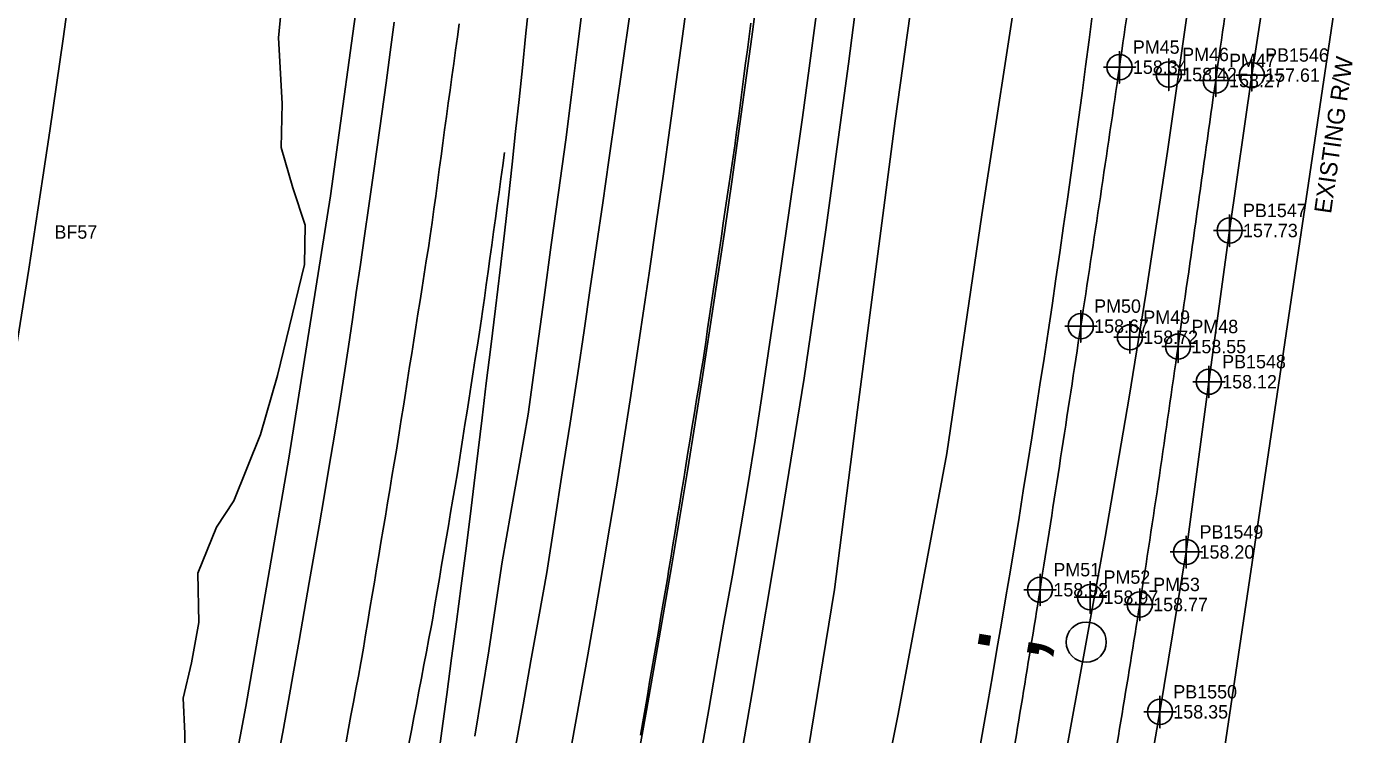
# Model space of a CAD drawing. Extents: x 2262665 to 2270527, y 505476 to 514960.
# Drawn here: x 2266157.3 to 2266407.4, y 509846.4 to 509978.6 of the extents above; entities that cross this region are included whole.
import ezdxf

# ---------------------------------------------------------------- set-up
doc = ezdxf.new("R2010")
doc.units = 0
for name, color, linetype in [('Exist DTM Crownline Cogo Elevation', 7, 'Continuous'), ('Exist DTM Crownline Cogo Number', 7, 'Continuous'), ('Exist DTM Crownline Cogo Point CELL', 7, 'Continuous'), ('Exist Guardrail', 7, 'Continuous'), ('Exist Horizontal Alignment', 7, 'Continuous'), ('Exist Property Corner Cogo Number', 7, 'Continuous'), ('Exist Right of Way Control of Access Line', 7, 'Continuous'), ('Exist Right of Way Line', 7, 'Continuous'), ('Exist Right of Way Line Text', 7, 'Continuous'), ('Exist Roads EOP', 7, 'Continuous'), ('Exist Roads EOP Cogo Elevation', 7, 'Continuous'), ('Exist Roads EOP Cogo Number', 7, 'Continuous'), ('Exist Roads EOP Cogo Point CELL', 7, 'Continuous'), ('Exist Roads EOT', 7, 'Continuous'), ('Exist Structure Minor Paved Ditch or Gutter', 7, 'Continuous'), ('Exist Utilities Water UG Line SUE LOS B', 7, 'Continuous'), ('Exist Utilities Water UG Line SUE LOS B Cogo Elevation', 7, 'Continuous'), ('Exist Utilities Water UG Line SUE LOS B Cogo Number', 7, 'Continuous'), ('Exist Utilities Water UG Line SUE LOS B Cogo Point CELL', 7, 'Continuous'), ('Exist Vegetation Hedge Row', 7, 'Continuous'), ('Exist Vegetation Woods Line', 7, 'Continuous'), ('Scratch_Level_1', 7, 'Continuous')]:
    doc.layers.add(name, color=color, linetype=linetype)

msp = doc.modelspace()

# ---------------------------------------------------------------- linework, layer by layer
at = {"layer": 'Exist DTM Crownline Cogo Point CELL'}
for points in [[(2266370.67, 509972.68), (2266370.67, 509966.68), (2266370.67, 509969.68), (2266373.67, 509969.68), (2266367.67, 509969.68)], [(2266363.41, 509923.59), (2266363.41, 509917.59), (2266363.41, 509920.59), (2266366.41, 509920.59), (2266360.41, 509920.59)], [(2266355.98, 509875.03), (2266355.98, 509869.03), (2266355.98, 509872.03), (2266358.98, 509872.03), (2266352.98, 509872.03)]]:
    msp.add_lwpolyline(points, dxfattribs=at)
for centre in [(2266370.67, 509969.68), (2266363.41, 509920.59), (2266355.98, 509872.03)]:
    msp.add_circle(centre, 2.34, dxfattribs=at)
at = {"layer": 'Exist Guardrail'}
for points in [[(2266160.84, 509676.92), (2266165.08, 509693.72), (2266174.04, 509733.83), (2266182.53, 509771.8), (2266190.31, 509809.74), (2266198.21, 509851.61), (2266206.26, 509898.03), (2266214.05, 509947), (2266219.83, 509989.18), (2266225.03, 510032.89), (2266230.21, 510077.92), (2266233.96, 510117.98), (2266237.41, 510165.42), (2266240.43, 510208.57), (2266242.31, 510234.33)], [(2266334.39, 510233.28), (2266333.37, 510212.85), (2266331.81, 510184.43), (2266330.09, 510160.21), (2266327.64, 510127.74), (2266324.86, 510095.33), (2266321.82, 510063.37), (2266317.9, 510027.29), (2266314.72, 510001.82), (2266310.83, 509971.64), (2266306.61, 509940.64), (2266302.52, 509912.93), (2266297.99, 509884.97), (2266292.86, 509854.22), (2266287.18, 509821.48), (2266279.3, 509783.63), (2266270.08, 509740.16), (2266261.99, 509703.88), (2266253.35, 509666.68), (2266250.16, 509652.66)]]:
    msp.add_lwpolyline(points, dxfattribs=at)
at = {"layer": 'Exist Horizontal Alignment'}
msp.add_line((2266331.51, 509734.43), (2266355.25, 509863.64), dxfattribs=at)
msp.add_circle((2266355.25, 509863.64), 3.75, dxfattribs=at)
for centre, radius, start, end in [((2263773.45, 510337.89), 2625, 349.59137, 358.85635), ((2263436.25, 510359.19), 2882, 309.60499, 355.6461)]:
    msp.add_arc(centre, radius, start, end, dxfattribs=at)
at = {"layer": 'Exist Right of Way Control of Access Line'}
msp.add_arc((2263436.25, 510359.19), 2754.56, 309.60499, 355.6461, dxfattribs=at)
at = {"layer": 'Exist Right of Way Line'}
msp.add_line((2266407.37, 510020.95), (2266379.14, 509830.83), dxfattribs=at)
at = {"layer": 'Exist Roads EOP'}
for points in [[(2266259.16, 509844.7), (2266260.64, 509852.99), (2266262.11, 509861.26), (2266263.56, 509869.51), (2266264.95, 509877.53), (2266266.26, 509885.3), (2266267.52, 509892.95), (2266268.73, 509900.58), (2266270.02, 509908.91), (2266271.4, 509917.99), (2266272.83, 509927.58), (2266273.56, 509932.54), (2266274.97, 509942.22), (2266276.24, 509951.15), (2266277.44, 509959.71), (2266278.63, 509968.3), (2266279.81, 509976.82), (2266280.96, 509985.2)], [(2266251.1, 509982.65), (2266250.5, 509976.8), (2266249.9, 509970.94), (2266249.28, 509965.01), (2266248.64, 509959), (2266247.98, 509952.91), (2266247.28, 509946.63), (2266246.53, 509940.05), (2266245.72, 509933.17), (2266244.86, 509925.99), (2266243.99, 509918.83), (2266243.16, 509912.02), (2266242.38, 509905.54), (2266241.64, 509899.41), (2266240.9, 509893.36), (2266240.13, 509887.12), (2266239.31, 509880.71), (2266238.45, 509874.12), (2266237.57, 509867.41), (2266236.67, 509860.66), (2266235.77, 509853.87), (2266234.85, 509847.03), (2266233.91, 509840.1)], [(2266225.97, 509979.46), (2266225.22, 509973.86), (2266224.44, 509968.11), (2266223.64, 509962.31), (2266222.83, 509956.54), (2266222.03, 509950.82), (2266221.21, 509945.13), (2266220.41, 509939.56), (2266219.63, 509934.16), (2266218.87, 509928.94), (2266218.14, 509923.9), (2266217.39, 509918.84), (2266216.58, 509913.55), (2266215.71, 509908.03), (2266214.78, 509902.27), (2266213.82, 509896.49), (2266212.88, 509890.85), (2266211.94, 509885.37), (2266211.02, 509880.04), (2266210.09, 509874.75), (2266209.15, 509869.38), (2266208.19, 509863.93), (2266207.21, 509858.4), (2266206.2, 509852.73), (2266205.12, 509846.83), (2266203.98, 509840.72)], [(2266304.76, 509980.71), (2266303.5, 509970.88), (2266302.24, 509961.65), (2266301.01, 509952.94), (2266299.82, 509944.68), (2266298.63, 509936.57), (2266297.41, 509928.3), (2266296.14, 509919.66), (2266294.76, 509910.42), (2266293.38, 509901.36), (2266292.09, 509893.28), (2266290.73, 509885.2), (2266289.13, 509876.12), (2266287.49, 509866.98), (2266286.04, 509858.71), (2266284.71, 509851.04), (2266283.4, 509843.7)]]:
    msp.add_lwpolyline(points, dxfattribs=at)
for points in [[(2266387.02, 510213.77), (2266383.96, 510164.13), (2266379.47, 510113.75), (2266374, 510066.49), (2266368.14, 510019.35), (2266361.46, 509971.05), (2266354.23, 509922.66), (2266346.61, 509873.42), (2266339.5, 509830.06)], [(2266405.94, 510212.74), (2266402.45, 510162.89), (2266397.89, 510112.57), (2266392.37, 510064.61), (2266386.2, 510016.82), (2266379.43, 509968.56), (2266372.4, 509918.85), (2266365.25, 509870.66), (2266358.04, 509827.1)]]:
    msp.add_spline(points, degree=3, dxfattribs=at)
at = {"layer": 'Exist Roads EOP Cogo Point CELL'}
for points in [[(2266361.46, 509974.05), (2266361.46, 509968.05), (2266361.46, 509971.05), (2266364.46, 509971.05), (2266358.46, 509971.05)], [(2266379.43, 509971.56), (2266379.43, 509965.56), (2266379.43, 509968.56), (2266382.43, 509968.56), (2266376.43, 509968.56)], [(2266354.23, 509925.66), (2266354.23, 509919.66), (2266354.23, 509922.66), (2266357.23, 509922.66), (2266351.23, 509922.66)], [(2266372.4, 509921.85), (2266372.4, 509915.85), (2266372.4, 509918.85), (2266375.4, 509918.85), (2266369.4, 509918.85)], [(2266346.61, 509876.42), (2266346.61, 509870.42), (2266346.61, 509873.42), (2266349.61, 509873.42), (2266343.61, 509873.42)], [(2266365.25, 509873.66), (2266365.25, 509867.66), (2266365.25, 509870.66), (2266368.25, 509870.66), (2266362.25, 509870.66)]]:
    msp.add_lwpolyline(points, dxfattribs=at)
for centre in [(2266361.46, 509971.05), (2266379.43, 509968.56), (2266354.23, 509922.66), (2266372.4, 509918.85), (2266346.61, 509873.42), (2266365.25, 509870.66)]:
    msp.add_circle(centre, 2.34, dxfattribs=at)
at = {"layer": 'Exist Roads EOT'}
for points in [[(2266292.57, 509979.25), (2266292.25, 509976.77), (2266291.93, 509974.29), (2266291.6, 509971.82), (2266291.28, 509969.34), (2266290.96, 509966.86), (2266290.63, 509964.38), (2266290.31, 509961.9), (2266289.99, 509959.42), (2266289.66, 509956.94), (2266289.64, 509956.76), (2266289.27, 509954.28), (2266288.91, 509951.81), (2266288.54, 509949.34), (2266288.17, 509946.86), (2266287.81, 509944.39), (2266287.44, 509941.92), (2266287.08, 509939.45), (2266286.71, 509936.97), (2266286.34, 509934.5), (2266285.98, 509932.03), (2266285.61, 509929.55), (2266285.25, 509927.08), (2266284.88, 509924.61), (2266284.51, 509922.14), (2266284.15, 509919.66), (2266283.78, 509917.19), (2266283.66, 509916.34), (2266283.26, 509913.88), (2266282.85, 509911.41), (2266282.45, 509908.94), (2266282.05, 509906.47), (2266281.65, 509904.01), (2266281.25, 509901.54), (2266280.84, 509899.07), (2266280.44, 509896.61), (2266280.04, 509894.14), (2266279.64, 509891.67), (2266279.23, 509889.2), (2266278.83, 509886.74), (2266278.43, 509884.27), (2266278.03, 509881.8), (2266277.63, 509879.34), (2266277.22, 509876.87), (2266277.06, 509875.84), (2266276.63, 509873.37), (2266276.21, 509870.91), (2266275.79, 509868.45), (2266275.37, 509865.98), (2266274.94, 509863.52), (2266274.52, 509861.05), (2266274.1, 509858.59), (2266273.68, 509856.13), (2266273.25, 509853.66), (2266272.83, 509851.2), (2266272.41, 509848.74), (2266271.98, 509846.27)], [(2266216.96, 509845.02), (2266217.42, 509847.47), (2266217.88, 509849.93), (2266218.34, 509852.39), (2266218.8, 509854.84), (2266219.26, 509857.3), (2266219.72, 509859.76), (2266219.78, 509860.06), (2266220.19, 509862.53), (2266220.6, 509864.99), (2266221.01, 509867.46), (2266221.43, 509869.93), (2266221.84, 509872.39), (2266222.25, 509874.86), (2266222.66, 509877.32), (2266223.07, 509879.79), (2266223.48, 509882.25), (2266223.9, 509884.72), (2266224.31, 509887.18), (2266224.72, 509889.65), (2266225.13, 509892.11), (2266225.54, 509894.58), (2266225.96, 509897.04), (2266226.37, 509899.51), (2266226.5, 509900.28), (2266226.89, 509902.75), (2266227.28, 509905.22), (2266227.66, 509907.69), (2266228.05, 509910.16), (2266228.44, 509912.63), (2266228.83, 509915.1), (2266229.22, 509917.57), (2266229.61, 509920.03), (2266230, 509922.5), (2266230.39, 509924.97), (2266230.78, 509927.44), (2266231.17, 509929.91), (2266231.56, 509932.38), (2266231.95, 509934.85), (2266232.34, 509937.32), (2266232.69, 509939.53), (2266233.02, 509942.01), (2266233.36, 509944.49), (2266233.7, 509946.97), (2266234.03, 509949.44), (2266234.37, 509951.92), (2266234.71, 509954.4), (2266235.05, 509956.87), (2266235.38, 509959.35), (2266235.72, 509961.83), (2266236.06, 509964.3), (2266236.4, 509966.78), (2266236.73, 509969.26), (2266237.07, 509971.73), (2266237.41, 509974.21), (2266237.75, 509976.69), (2266238.08, 509979.16)], [(2266246.58, 509955.13), (2266246.24, 509952.66), (2266245.89, 509950.18), (2266245.55, 509947.71), (2266245.21, 509945.23), (2266244.86, 509942.75), (2266244.52, 509940.28), (2266244.18, 509937.8), (2266243.83, 509935.33), (2266243.49, 509932.85), (2266243.15, 509930.37), (2266242.8, 509927.9), (2266242.46, 509925.42), (2266242.27, 509924.04), (2266241.88, 509921.57), (2266241.49, 509919.1), (2266241.11, 509916.63), (2266240.72, 509914.16), (2266240.34, 509911.69), (2266239.95, 509909.23), (2266239.56, 509906.76), (2266239.18, 509904.29), (2266238.79, 509901.82), (2266238.41, 509899.35), (2266238.02, 509896.88), (2266237.76, 509895.24), (2266237.34, 509892.77), (2266236.92, 509890.31), (2266236.5, 509887.85), (2266236.08, 509885.38), (2266235.66, 509882.92), (2266235.24, 509880.45), (2266234.82, 509877.99), (2266234.4, 509875.53), (2266233.98, 509873.06), (2266233.56, 509870.6), (2266233.14, 509868.13), (2266232.91, 509866.74), (2266232.44, 509864.28), (2266231.97, 509861.83), (2266231.51, 509859.37), (2266231.04, 509856.92), (2266230.57, 509854.46), (2266230.1, 509852.01), (2266229.64, 509849.55), (2266229.17, 509847.1), (2266228.7, 509844.64)]]:
    msp.add_lwpolyline(points, dxfattribs=at)
at = {"layer": 'Exist Structure Minor Paved Ditch or Gutter'}
for points in [[(2266241.03, 509846.09), (2266242.34, 509854.05), (2266243.66, 509862.01), (2266244.89, 509870.32), (2266246.11, 509878.63), (2266247.75, 509887.82), (2266249.38, 509897.01), (2266251.01, 509906.21), (2266251.99, 509913.49), (2266252.97, 509920.77), (2266253.95, 509928.04), (2266255.3, 509937.85), (2266256.65, 509947.65), (2266257.99, 509957.45), (2266259.07, 509965.89), (2266260.15, 509974.32), (2266261.22, 509982.76)], [(2266269.99, 509980.92), (2266268.68, 509971.83), (2266267.37, 509962.74), (2266266.06, 509953.65), (2266264.91, 509945.7), (2266263.75, 509937.74), (2266262.59, 509929.79), (2266261.43, 509921.84), (2266260.27, 509913.88), (2266258.82, 509904.56), (2266257.36, 509895.24), (2266255.9, 509885.93), (2266254.45, 509876.61), (2266252.97, 509868.37), (2266251.5, 509860.14), (2266250.03, 509851.9), (2266248.56, 509843.67)]]:
    msp.add_lwpolyline(points, dxfattribs=at)
at = {"layer": 'Exist Utilities Water UG Line SUE LOS B'}
msp.add_lwpolyline([(2266275.52, 509476.49), (2266281.48, 509492.88), (2266288.61, 509514.28), (2266295.01, 509530.67), (2266307.18, 509564.42), (2266312.74, 509581.53), (2266318.23, 509600.17), (2266322.52, 509615.5), (2266323.02, 509617.11), (2266327.09, 509634.63), (2266333.26, 509660.07), (2266338.73, 509684.45), (2266344.64, 509710.13), (2266349.6, 509737.28), (2266354.11, 509761.83), (2266358.6, 509789.84), (2266363.32, 509817.94), (2266369.02, 509850.61), (2266373.92, 509880.48), (2266378.15, 509912.28), (2266382.04, 509940.53), (2266386.17, 509969.57), (2266389.96, 509994.37)], dxfattribs=at)
at = {"layer": 'Exist Utilities Water UG Line SUE LOS B Cogo Point CELL'}
for points in [[(2266386.17, 509972.57), (2266386.17, 509966.57), (2266386.17, 509969.57), (2266389.17, 509969.57), (2266383.17, 509969.57)], [(2266382.04, 509943.53), (2266382.04, 509937.53), (2266382.04, 509940.53), (2266385.04, 509940.53), (2266379.04, 509940.53)], [(2266378.15, 509915.28), (2266378.15, 509909.28), (2266378.15, 509912.28), (2266381.15, 509912.28), (2266375.15, 509912.28)], [(2266373.92, 509883.48), (2266373.92, 509877.48), (2266373.92, 509880.48), (2266376.92, 509880.48), (2266370.92, 509880.48)], [(2266369.02, 509853.61), (2266369.02, 509847.61), (2266369.02, 509850.61), (2266372.02, 509850.61), (2266366.02, 509850.61)]]:
    msp.add_lwpolyline(points, dxfattribs=at)
for centre in [(2266386.17, 509969.57), (2266382.04, 509940.53), (2266378.15, 509912.28), (2266373.92, 509880.48), (2266369.02, 509850.61)]:
    msp.add_circle(centre, 2.34, dxfattribs=at)
at = {"layer": 'Exist Vegetation Hedge Row'}
msp.add_lwpolyline([(2266342.93, 509989.96), (2266335.75, 509943.47), (2266329.22, 509898.87), (2266320.09, 509850.17), (2266310.71, 509803.13), (2266299.92, 509750.24), (2266287.31, 509699), (2266274.41, 509653.77), (2266262.16, 509616.12), (2266260.35, 509610.04), (2266258.91, 509607.46), (2266257.84, 509606.29), (2266255.21, 509607.29), (2266254.06, 509611.99), (2266254.72, 509621.39), (2266270.87, 509684.34), (2266285.22, 509743.81), (2266291.88, 509776.64), (2266296.56, 509801.15), (2266301.19, 509830.41), (2266308.19, 509873.45), (2266312.53, 509907.02), (2266319.57, 509961.03), (2266328.36, 510023.72)], dxfattribs=at)
at = {"layer": 'Exist Vegetation Woods Line'}
msp.add_lwpolyline([(2266204.8, 509981.08), (2266204.32, 509976.55), (2266204.99, 509964.23), (2266204.86, 509956.05), (2266207.01, 509948.51), (2266209.29, 509941.55), (2266209.17, 509934.18), (2266204.15, 509913.46), (2266200.98, 509902.43), (2266195.97, 509890.05), (2266192.78, 509885.08), (2266189.28, 509876.52), (2266189.48, 509867.27), (2266188.08, 509859.74), (2266186.5, 509853.19), (2266186.83, 509846.59), (2266186.86, 509842.75)], dxfattribs=at)
at = {"layer": 'Scratch_Level_1'}
msp.add_line((2266339.89, 509868.2), (2266339.89, 509868.2), dxfattribs=at)
msp.add_arc((2263436.25, 510359.19), 2944.56, 343.16776, 355.6461, dxfattribs=at)

# ---------------------------------------------------------------- texts
at = {"layer": 'Exist DTM Crownline Cogo Elevation'}
for s, p in [('158.42', (2266373.17, 509968.43)), ('158.72', (2266365.91, 509919.34)), ('158.97', (2266358.48, 509870.78))]:
    msp.add_text(s, height=2.5, dxfattribs=at).set_placement(p)
at = {"layer": 'Exist DTM Crownline Cogo Number'}
for s, p in [('PM46', (2266373.17, 509972.18)), ('PM49', (2266365.91, 509923.09)), ('PM52', (2266358.48, 509874.53))]:
    msp.add_text(s, height=2.5, dxfattribs=at).set_placement(p)
at = {"layer": 'Exist Property Corner Cogo Number'}
msp.add_text('BF57', height=2.5, dxfattribs=at).set_placement((2266162.48, 509939))
at = {"layer": 'Exist Right of Way Line Text'}
msp.add_text('EXISTING R/W', height=3.2, rotation=81.9122, dxfattribs=at).set_placement((2266400.98, 509943.57))
at = {"layer": 'Exist Roads EOP Cogo Elevation'}
for s, p in [('158.34', (2266363.96, 509969.8)), ('158.27', (2266381.93, 509967.31)), ('158.67', (2266356.73, 509921.41)), ('158.55', (2266374.9, 509917.6)), ('158.92', (2266349.11, 509872.17)), ('158.77', (2266367.75, 509869.41))]:
    msp.add_text(s, height=2.5, dxfattribs=at).set_placement(p)
at = {"layer": 'Exist Roads EOP Cogo Number'}
for s, p in [('PM45', (2266363.96, 509973.55)), ('PM47', (2266381.93, 509971.06)), ('PM50', (2266356.73, 509925.16)), ('PM48', (2266374.9, 509921.35)), ('PM51', (2266349.11, 509875.92)), ('PM53', (2266367.75, 509873.16))]:
    msp.add_text(s, height=2.5, dxfattribs=at).set_placement(p)
at = {"layer": 'Exist Utilities Water UG Line SUE LOS B Cogo Elevation'}
for s, p in [('157.61', (2266388.67, 509968.32)), ('157.73', (2266384.54, 509939.28)), ('158.12', (2266380.65, 509911.03)), ('158.20', (2266376.42, 509879.23)), ('158.35', (2266371.52, 509849.36))]:
    msp.add_text(s, height=2.5, dxfattribs=at).set_placement(p)
at = {"layer": 'Exist Utilities Water UG Line SUE LOS B Cogo Number'}
for s, p in [('PB1546', (2266388.67, 509972.07)), ('PB1547', (2266384.54, 509943.03)), ('PB1548', (2266380.65, 509914.78)), ('PB1549', (2266376.42, 509882.98)), ('PB1550', (2266371.52, 509853.11))]:
    msp.add_text(s, height=2.5, dxfattribs=at).set_placement(p)
at = {"layer": 'Scratch_Level_1'}
msp.add_text(';', height=15, rotation=80.3943, dxfattribs=at).set_placement((2266346.03, 509859.56))

doc.saveas('drawing.dxf')
